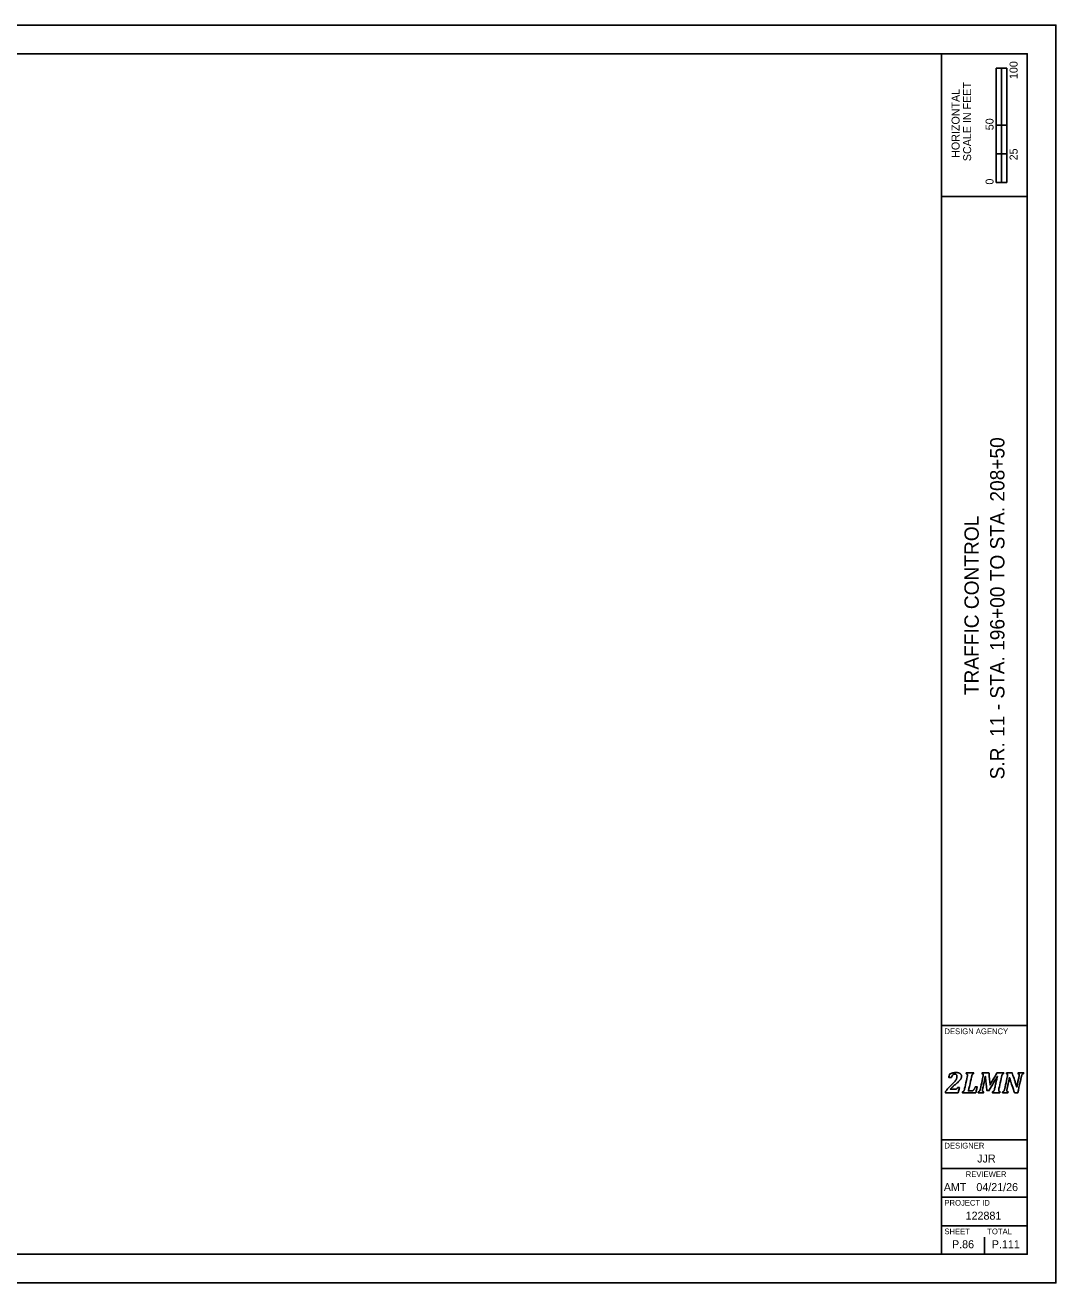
# Model space of a CAD drawing. Extents: x -2.1 to 34, y 0 to 22.
# Drawn here: x 15.96 to 34, y 0 to 22 of the extents above; entities that cross this region are included whole.
import ezdxf

# ---------------------------------------------------------------- set-up
doc = ezdxf.new("R2010")
doc.units = 0
for name, color, linetype in [('SH_Border', 7, 'Continuous'), ('SH_Cut_Line', 7, 'Continuous'), ('SH_Data', 7, 'Continuous')]:
    doc.layers.add(name, color=color, linetype=linetype)

msp = doc.modelspace()

# ---------------------------------------------------------------- linework, layer by layer
at = {"layer": 'SH_Border'}
for p, q in [((32, 0.5), (32, 21.5)), ((32, 19), (33.5, 19)), ((32, 4.5), (33.5, 4.5)), ((32, 2.5), (33.5, 2.5)), ((32, 2), (33.5, 2)), ((32, 1.5), (33.5, 1.5)), ((32, 1), (33.5, 1))]:
    msp.add_line(p, q, dxfattribs=at)
msp.add_lwpolyline([(1.5, 21.5), (33.5, 21.5), (33.5, 0.5), (1.5, 0.5)], close=True, dxfattribs=at)
at = {"layer": 'SH_Cut_Line'}
msp.add_lwpolyline([(0, 0), (34, 0), (34, 22), (0, 22)], close=True, dxfattribs=at)
at = {"layer": 'SH_Data'}
for p, q in [((32.957, 19.25), (32.957, 21.25)), ((33.144, 21.25), (32.957, 21.25)), ((32.957, 20.25), (32.957, 21.25)), ((32.957, 21.25), (33.05, 21.25)), ((33.05, 21.25), (33.051, 21.25)), ((33.051, 21.25), (33.051, 20.25)), ((33.144, 21.25), (33.144, 19.25)), ((33.051, 20.25), (32.957, 20.25)), ((33.143, 20.25), (33.05, 20.25)), ((33.05, 20.25), (33.05, 19.75)), ((33.143, 19.75), (33.143, 20.25)), ((33.05, 19.75), (32.957, 19.75)), ((32.957, 19.75), (32.957, 19.25)), ((33.05, 19.25), (33.05, 19.75)), ((33.05, 19.75), (33.143, 19.75)), ((33.144, 19.25), (32.957, 19.25)), ((32.957, 19.25), (33.05, 19.25)), ((32.75, 3.5), (32.75, 3.5)), ((32.375, 0.675), (32.375, 0.675)), ((32.75, 0.5), (32.75, 0.8))]:
    msp.add_line(p, q, dxfattribs=at)
for points in [[(32.237, 3.388), (32.246, 3.388), (32.253, 3.389), (32.258, 3.39), (32.263, 3.392), (32.267, 3.394), (32.27, 3.397), (32.273, 3.401), (32.277, 3.408), (32.281, 3.417), (32.281, 3.417), (32.312, 3.417), (32.312, 3.417), (32.312, 3.417), (32.29, 3.326), (32.29, 3.326), (32.29, 3.326), (32.066, 3.326), (32.066, 3.326), (32.066, 3.326), (32.069, 3.343), (32.069, 3.343), (32.078, 3.358), (32.091, 3.375), (32.106, 3.394), (32.122, 3.412), (32.144, 3.435), (32.172, 3.462), (32.197, 3.486), (32.217, 3.506), (32.23, 3.521), (32.243, 3.537), (32.253, 3.551), (32.259, 3.566), (32.266, 3.58), (32.269, 3.595), (32.269, 3.61), (32.269, 3.622), (32.266, 3.632), (32.26, 3.64), (32.253, 3.647), (32.245, 3.65), (32.234, 3.65), (32.22, 3.65), (32.208, 3.646), (32.198, 3.636), (32.188, 3.627), (32.18, 3.613), (32.172, 3.593), (32.172, 3.593), (32.126, 3.593), (32.126, 3.593), (32.126, 3.593), (32.14, 3.654), (32.14, 3.654), (32.166, 3.663), (32.188, 3.669), (32.205, 3.673), (32.223, 3.676), (32.24, 3.678), (32.258, 3.678), (32.278, 3.678), (32.295, 3.675), (32.309, 3.669), (32.322, 3.664), (32.332, 3.656), (32.339, 3.646), (32.345, 3.637), (32.348, 3.626), (32.348, 3.613), (32.348, 3.602), (32.346, 3.591), (32.342, 3.581), (32.339, 3.571), (32.333, 3.56), (32.324, 3.549), (32.315, 3.539), (32.304, 3.526), (32.289, 3.513), (32.275, 3.499), (32.254, 3.482), (32.228, 3.46), (32.216, 3.45), (32.202, 3.438), (32.188, 3.425), (32.174, 3.412), (32.162, 3.4), (32.154, 3.391), (32.154, 3.391), (32.153, 3.388), (32.153, 3.388), (32.153, 3.388), (32.237, 3.388), (32.237, 3.388)], [(32.237, 3.388), (32.237, 3.388), (32.153, 3.388), (32.153, 3.388), (32.153, 3.388), (32.154, 3.391), (32.154, 3.391), (32.162, 3.4), (32.174, 3.412), (32.188, 3.425), (32.202, 3.438), (32.216, 3.45), (32.228, 3.46), (32.254, 3.482), (32.275, 3.499), (32.289, 3.513), (32.304, 3.526), (32.315, 3.539), (32.324, 3.549), (32.333, 3.56), (32.339, 3.571), (32.342, 3.581), (32.346, 3.591), (32.348, 3.602), (32.348, 3.613), (32.348, 3.626), (32.345, 3.637), (32.339, 3.646), (32.332, 3.656), (32.322, 3.664), (32.309, 3.669), (32.295, 3.675), (32.278, 3.678), (32.258, 3.678), (32.24, 3.678), (32.223, 3.676), (32.205, 3.673), (32.188, 3.669), (32.166, 3.663), (32.14, 3.654), (32.14, 3.654), (32.126, 3.593), (32.126, 3.593), (32.126, 3.593), (32.172, 3.593), (32.172, 3.593), (32.18, 3.613), (32.188, 3.627), (32.198, 3.636), (32.208, 3.646), (32.22, 3.65), (32.234, 3.65), (32.245, 3.65), (32.253, 3.647), (32.26, 3.64), (32.266, 3.632), (32.269, 3.622), (32.269, 3.61), (32.269, 3.595), (32.266, 3.58), (32.259, 3.566), (32.253, 3.551), (32.243, 3.537), (32.23, 3.521), (32.217, 3.506), (32.197, 3.486), (32.172, 3.462), (32.144, 3.435), (32.122, 3.412), (32.106, 3.394), (32.091, 3.375), (32.078, 3.358), (32.069, 3.343), (32.069, 3.343), (32.066, 3.326), (32.066, 3.326), (32.066, 3.326), (32.29, 3.326), (32.29, 3.326), (32.29, 3.326), (32.312, 3.417), (32.312, 3.417), (32.312, 3.417), (32.281, 3.417), (32.281, 3.417), (32.277, 3.408), (32.273, 3.401), (32.27, 3.397), (32.267, 3.394), (32.263, 3.392), (32.258, 3.39), (32.253, 3.389), (32.246, 3.388), (32.237, 3.388)], [(32.518, 3.356), (32.527, 3.356), (32.533, 3.357), (32.538, 3.358), (32.542, 3.36), (32.546, 3.362), (32.55, 3.365), (32.554, 3.368), (32.558, 3.372), (32.562, 3.377), (32.567, 3.382), (32.571, 3.388), (32.576, 3.397), (32.58, 3.405), (32.585, 3.415), (32.589, 3.427), (32.589, 3.427), (32.624, 3.427), (32.624, 3.427), (32.624, 3.427), (32.598, 3.326), (32.598, 3.326), (32.598, 3.326), (32.365, 3.326), (32.365, 3.326), (32.365, 3.326), (32.369, 3.343), (32.369, 3.343), (32.376, 3.345), (32.381, 3.348), (32.385, 3.351), (32.389, 3.355), (32.392, 3.36), (32.395, 3.366), (32.398, 3.373), (32.4, 3.382), (32.403, 3.395), (32.403, 3.395), (32.449, 3.605), (32.449, 3.605), (32.452, 3.615), (32.453, 3.625), (32.453, 3.635), (32.453, 3.642), (32.451, 3.647), (32.448, 3.651), (32.444, 3.654), (32.439, 3.656), (32.432, 3.657), (32.432, 3.657), (32.435, 3.674), (32.435, 3.674), (32.435, 3.674), (32.563, 3.674), (32.563, 3.674), (32.563, 3.674), (32.559, 3.657), (32.559, 3.657), (32.552, 3.655), (32.547, 3.652), (32.543, 3.649), (32.539, 3.645), (32.536, 3.64), (32.533, 3.634), (32.531, 3.627), (32.528, 3.618), (32.525, 3.605), (32.525, 3.605), (32.47, 3.356), (32.47, 3.356), (32.47, 3.356), (32.518, 3.356), (32.518, 3.356)], [(32.518, 3.356), (32.518, 3.356), (32.47, 3.356), (32.47, 3.356), (32.47, 3.356), (32.525, 3.605), (32.525, 3.605), (32.528, 3.618), (32.531, 3.627), (32.533, 3.634), (32.536, 3.64), (32.539, 3.645), (32.543, 3.649), (32.547, 3.652), (32.552, 3.655), (32.559, 3.657), (32.559, 3.657), (32.563, 3.674), (32.563, 3.674), (32.563, 3.674), (32.435, 3.674), (32.435, 3.674), (32.435, 3.674), (32.432, 3.657), (32.432, 3.657), (32.439, 3.656), (32.444, 3.654), (32.448, 3.651), (32.451, 3.647), (32.453, 3.642), (32.453, 3.635), (32.453, 3.625), (32.452, 3.615), (32.449, 3.605), (32.449, 3.605), (32.403, 3.395), (32.403, 3.395), (32.4, 3.382), (32.398, 3.373), (32.395, 3.366), (32.392, 3.36), (32.389, 3.355), (32.385, 3.351), (32.381, 3.348), (32.376, 3.345), (32.369, 3.343), (32.369, 3.343), (32.365, 3.326), (32.365, 3.326), (32.365, 3.326), (32.598, 3.326), (32.598, 3.326), (32.598, 3.326), (32.624, 3.427), (32.624, 3.427), (32.624, 3.427), (32.589, 3.427), (32.589, 3.427), (32.585, 3.415), (32.58, 3.405), (32.576, 3.397), (32.571, 3.388), (32.567, 3.382), (32.562, 3.377), (32.558, 3.372), (32.554, 3.368), (32.55, 3.365), (32.546, 3.362), (32.542, 3.36), (32.538, 3.358), (32.533, 3.357), (32.527, 3.356), (32.518, 3.356)], [(32.829, 3.674), (32.829, 3.674), (32.849, 3.461), (32.849, 3.461), (32.849, 3.461), (32.969, 3.674), (32.969, 3.674), (32.969, 3.674), (33.087, 3.674), (33.087, 3.674), (33.087, 3.674), (33.084, 3.657), (33.084, 3.657), (33.077, 3.655), (33.071, 3.652), (33.067, 3.649), (33.064, 3.645), (33.06, 3.64), (33.058, 3.634), (33.055, 3.627), (33.052, 3.618), (33.05, 3.605), (33.05, 3.605), (33.003, 3.395), (33.003, 3.395), (33.002, 3.39), (33.002, 3.387), (33.001, 3.384), (33.001, 3.382), (33.001, 3.379), (33, 3.376), (33, 3.373), (33, 3.369), (33, 3.365), (33, 3.358), (33.002, 3.353), (33.005, 3.349), (33.008, 3.346), (33.014, 3.344), (33.021, 3.343), (33.021, 3.343), (33.018, 3.326), (33.018, 3.326), (33.018, 3.326), (32.89, 3.326), (32.89, 3.326), (32.89, 3.326), (32.893, 3.343), (32.893, 3.343), (32.9, 3.345), (32.906, 3.348), (32.91, 3.351), (32.914, 3.355), (32.917, 3.36), (32.919, 3.366), (32.922, 3.373), (32.925, 3.382), (32.928, 3.395), (32.928, 3.395), (32.951, 3.502), (32.951, 3.502), (32.954, 3.513), (32.957, 3.529), (32.962, 3.548), (32.967, 3.568), (32.972, 3.588), (32.978, 3.609), (32.978, 3.609), (32.973, 3.609), (32.973, 3.609), (32.965, 3.594), (32.957, 3.579), (32.948, 3.563), (32.948, 3.563), (32.833, 3.364), (32.833, 3.364), (32.833, 3.364), (32.792, 3.364), (32.792, 3.364), (32.792, 3.364), (32.775, 3.518), (32.775, 3.518), (32.773, 3.537), (32.772, 3.554), (32.77, 3.569), (32.769, 3.583), (32.768, 3.597), (32.768, 3.611), (32.768, 3.611), (32.764, 3.611), (32.764, 3.611), (32.761, 3.596), (32.758, 3.578), (32.755, 3.558), (32.751, 3.538), (32.747, 3.521), (32.744, 3.507), (32.744, 3.507), (32.72, 3.395), (32.72, 3.395), (32.719, 3.39), (32.718, 3.387), (32.718, 3.384), (32.717, 3.382), (32.717, 3.379), (32.717, 3.376), (32.717, 3.373), (32.716, 3.369), (32.716, 3.365), (32.716, 3.358), (32.718, 3.353), (32.721, 3.349), (32.725, 3.346), (32.73, 3.344), (32.738, 3.343), (32.738, 3.343), (32.734, 3.326), (32.734, 3.326), (32.734, 3.326), (32.641, 3.326), (32.641, 3.326), (32.641, 3.326), (32.644, 3.343), (32.644, 3.343), (32.651, 3.345), (32.657, 3.348), (32.661, 3.351), (32.665, 3.355), (32.668, 3.36), (32.67, 3.366), (32.673, 3.373), (32.676, 3.382), (32.679, 3.395), (32.679, 3.395), (32.725, 3.605), (32.725, 3.605), (32.727, 3.615), (32.728, 3.625), (32.728, 3.635), (32.728, 3.642), (32.727, 3.647), (32.723, 3.651), (32.72, 3.654), (32.715, 3.656), (32.707, 3.657), (32.707, 3.657), (32.711, 3.674), (32.711, 3.674), (32.711, 3.674), (32.829, 3.674), (32.829, 3.674)], [(32.829, 3.674), (32.829, 3.674), (32.711, 3.674), (32.711, 3.674), (32.711, 3.674), (32.707, 3.657), (32.707, 3.657), (32.715, 3.656), (32.72, 3.654), (32.723, 3.651), (32.727, 3.647), (32.728, 3.642), (32.728, 3.635), (32.728, 3.625), (32.727, 3.615), (32.725, 3.605), (32.725, 3.605), (32.679, 3.395), (32.679, 3.395), (32.676, 3.382), (32.673, 3.373), (32.67, 3.366), (32.668, 3.36), (32.665, 3.355), (32.661, 3.351), (32.657, 3.348), (32.651, 3.345), (32.644, 3.343), (32.644, 3.343), (32.641, 3.326), (32.641, 3.326), (32.641, 3.326), (32.734, 3.326), (32.734, 3.326), (32.734, 3.326), (32.738, 3.343), (32.738, 3.343), (32.73, 3.344), (32.725, 3.346), (32.721, 3.349), (32.718, 3.353), (32.716, 3.358), (32.716, 3.365), (32.716, 3.369), (32.717, 3.373), (32.717, 3.376), (32.717, 3.379), (32.717, 3.382), (32.718, 3.384), (32.718, 3.387), (32.719, 3.39), (32.72, 3.395), (32.72, 3.395), (32.744, 3.507), (32.744, 3.507), (32.747, 3.521), (32.751, 3.538), (32.755, 3.558), (32.758, 3.578), (32.761, 3.596), (32.764, 3.611), (32.764, 3.611), (32.768, 3.611), (32.768, 3.611), (32.768, 3.597), (32.769, 3.583), (32.77, 3.569), (32.772, 3.554), (32.773, 3.537), (32.775, 3.518), (32.775, 3.518), (32.792, 3.364), (32.792, 3.364), (32.792, 3.364), (32.833, 3.364), (32.833, 3.364), (32.833, 3.364), (32.948, 3.563), (32.948, 3.563), (32.957, 3.579), (32.965, 3.594), (32.973, 3.609), (32.973, 3.609), (32.978, 3.609), (32.978, 3.609), (32.972, 3.588), (32.967, 3.568), (32.962, 3.548), (32.957, 3.529), (32.954, 3.513), (32.951, 3.502), (32.951, 3.502), (32.928, 3.395), (32.928, 3.395), (32.925, 3.382), (32.922, 3.373), (32.919, 3.366), (32.917, 3.36), (32.914, 3.355), (32.91, 3.351), (32.906, 3.348), (32.9, 3.345), (32.893, 3.343), (32.893, 3.343), (32.89, 3.326), (32.89, 3.326), (32.89, 3.326), (33.018, 3.326), (33.018, 3.326), (33.018, 3.326), (33.021, 3.343), (33.021, 3.343), (33.014, 3.344), (33.008, 3.346), (33.005, 3.349), (33.002, 3.353), (33, 3.358), (33, 3.365), (33, 3.369), (33, 3.373), (33, 3.376), (33.001, 3.379), (33.001, 3.382), (33.001, 3.384), (33.002, 3.387), (33.002, 3.39), (33.003, 3.395), (33.003, 3.395), (33.05, 3.605), (33.05, 3.605), (33.052, 3.618), (33.055, 3.627), (33.058, 3.634), (33.06, 3.64), (33.064, 3.645), (33.067, 3.649), (33.071, 3.652), (33.077, 3.655), (33.084, 3.657), (33.084, 3.657), (33.087, 3.674), (33.087, 3.674), (33.087, 3.674), (32.969, 3.674), (32.969, 3.674), (32.969, 3.674), (32.849, 3.461), (32.849, 3.461), (32.849, 3.461), (32.829, 3.674), (32.829, 3.674)], [(33.137, 3.674), (33.137, 3.674), (33.234, 3.674), (33.234, 3.674), (33.234, 3.674), (33.283, 3.53), (33.283, 3.53), (33.296, 3.49), (33.307, 3.456), (33.315, 3.426), (33.315, 3.426), (33.318, 3.426), (33.318, 3.426), (33.323, 3.455), (33.329, 3.488), (33.337, 3.523), (33.337, 3.523), (33.355, 3.605), (33.355, 3.605), (33.357, 3.615), (33.358, 3.625), (33.358, 3.635), (33.358, 3.642), (33.357, 3.647), (33.353, 3.651), (33.35, 3.654), (33.345, 3.656), (33.337, 3.657), (33.337, 3.657), (33.341, 3.674), (33.341, 3.674), (33.341, 3.674), (33.434, 3.674), (33.434, 3.674), (33.434, 3.674), (33.431, 3.657), (33.431, 3.657), (33.424, 3.655), (33.418, 3.652), (33.414, 3.649), (33.41, 3.645), (33.407, 3.64), (33.405, 3.634), (33.402, 3.627), (33.399, 3.618), (33.396, 3.605), (33.396, 3.605), (33.335, 3.326), (33.335, 3.326), (33.335, 3.326), (33.277, 3.326), (33.277, 3.326), (33.277, 3.326), (33.216, 3.504), (33.216, 3.504), (33.211, 3.518), (33.207, 3.531), (33.204, 3.543), (33.2, 3.556), (33.195, 3.571), (33.19, 3.59), (33.19, 3.59), (33.186, 3.59), (33.186, 3.59), (33.185, 3.579), (33.182, 3.563), (33.179, 3.543), (33.175, 3.523), (33.17, 3.501), (33.165, 3.478), (33.165, 3.478), (33.147, 3.395), (33.147, 3.395), (33.146, 3.39), (33.145, 3.387), (33.145, 3.384), (33.144, 3.382), (33.144, 3.379), (33.144, 3.376), (33.143, 3.373), (33.143, 3.369), (33.143, 3.365), (33.143, 3.358), (33.145, 3.353), (33.148, 3.349), (33.152, 3.346), (33.157, 3.344), (33.164, 3.343), (33.164, 3.343), (33.161, 3.326), (33.161, 3.326), (33.161, 3.326), (33.067, 3.326), (33.067, 3.326), (33.067, 3.326), (33.071, 3.343), (33.071, 3.343), (33.078, 3.345), (33.083, 3.348), (33.087, 3.351), (33.091, 3.355), (33.094, 3.36), (33.097, 3.366), (33.1, 3.373), (33.102, 3.382), (33.105, 3.395), (33.105, 3.395), (33.151, 3.605), (33.151, 3.605), (33.154, 3.615), (33.155, 3.625), (33.155, 3.635), (33.155, 3.642), (33.153, 3.647), (33.15, 3.651), (33.146, 3.654), (33.141, 3.656), (33.134, 3.657), (33.134, 3.657), (33.137, 3.674), (33.137, 3.674)], [(33.137, 3.674), (33.137, 3.674), (33.134, 3.657), (33.134, 3.657), (33.141, 3.656), (33.146, 3.654), (33.15, 3.651), (33.153, 3.647), (33.155, 3.642), (33.155, 3.635), (33.155, 3.625), (33.154, 3.615), (33.151, 3.605), (33.151, 3.605), (33.105, 3.395), (33.105, 3.395), (33.102, 3.382), (33.1, 3.373), (33.097, 3.366), (33.094, 3.36), (33.091, 3.355), (33.087, 3.351), (33.083, 3.348), (33.078, 3.345), (33.071, 3.343), (33.071, 3.343), (33.067, 3.326), (33.067, 3.326), (33.067, 3.326), (33.161, 3.326), (33.161, 3.326), (33.161, 3.326), (33.164, 3.343), (33.164, 3.343), (33.157, 3.344), (33.152, 3.346), (33.148, 3.349), (33.145, 3.353), (33.143, 3.358), (33.143, 3.365), (33.143, 3.369), (33.143, 3.373), (33.144, 3.376), (33.144, 3.379), (33.144, 3.382), (33.145, 3.384), (33.145, 3.387), (33.146, 3.39), (33.147, 3.395), (33.147, 3.395), (33.165, 3.478), (33.165, 3.478), (33.17, 3.501), (33.175, 3.523), (33.179, 3.543), (33.182, 3.563), (33.185, 3.579), (33.186, 3.59), (33.186, 3.59), (33.19, 3.59), (33.19, 3.59), (33.195, 3.571), (33.2, 3.556), (33.204, 3.543), (33.207, 3.531), (33.211, 3.518), (33.216, 3.504), (33.216, 3.504), (33.277, 3.326), (33.277, 3.326), (33.277, 3.326), (33.335, 3.326), (33.335, 3.326), (33.335, 3.326), (33.396, 3.605), (33.396, 3.605), (33.399, 3.618), (33.402, 3.627), (33.405, 3.634), (33.407, 3.64), (33.41, 3.645), (33.414, 3.649), (33.418, 3.652), (33.424, 3.655), (33.431, 3.657), (33.431, 3.657), (33.434, 3.674), (33.434, 3.674), (33.434, 3.674), (33.341, 3.674), (33.341, 3.674), (33.341, 3.674), (33.337, 3.657), (33.337, 3.657), (33.345, 3.656), (33.35, 3.654), (33.353, 3.651), (33.357, 3.647), (33.358, 3.642), (33.358, 3.635), (33.358, 3.625), (33.357, 3.615), (33.355, 3.605), (33.355, 3.605), (33.337, 3.523), (33.337, 3.523), (33.329, 3.488), (33.323, 3.455), (33.318, 3.426), (33.318, 3.426), (33.315, 3.426), (33.315, 3.426), (33.307, 3.456), (33.296, 3.49), (33.283, 3.53), (33.283, 3.53), (33.234, 3.674), (33.234, 3.674), (33.234, 3.674), (33.137, 3.674), (33.137, 3.674)]]:
    msp.add_open_spline(points, degree=3, dxfattribs=at)

# ---------------------------------------------------------------- texts
for s, height, p in [('100', 0.14, (33.33, 21.057)), ('SCALE IN FEET', 0.14, (32.517, 19.621)), ('HORIZONTAL', 0.14, (32.315, 19.679)), ('50', 0.14, (32.91, 20.162)), ('25', 0.14, (33.33, 19.635)), ('0', 0.14, (32.91, 19.211)), ('S.R. 11 - STA. 196+00 TO STA. 208+50', 0.25, (33.1, 8.807)), ('TRAFFIC CONTROL', 0.25, (32.65, 10.28))]:
    msp.add_text(s, height=height, rotation=90, dxfattribs=at).set_placement(p)
for s, height, p in [('DESIGN AGENCY', 0.1, (32.05, 4.35)), ('DESIGNER', 0.1, (32.05, 2.35)), ('JJR', 0.14, (32.624, 2.105)), ('REVIEWER', 0.1, (32.422, 1.85)), ('AMT', 0.14, (32.039, 1.605)), ('04/21/26', 0.14, (32.609, 1.605)), ('PROJECT ID', 0.1, (32.05, 1.35)), ('122881', 0.14, (32.421, 1.105)), ('SHEET', 0.1, (32.05, 0.85)), ('TOTAL', 0.1, (32.8, 0.85)), ('P.86', 0.14, (32.183, 0.605)), ('P.111', 0.14, (32.879, 0.605))]:
    msp.add_text(s, height=height, dxfattribs=at).set_placement(p)

doc.saveas('drawing.dxf')
